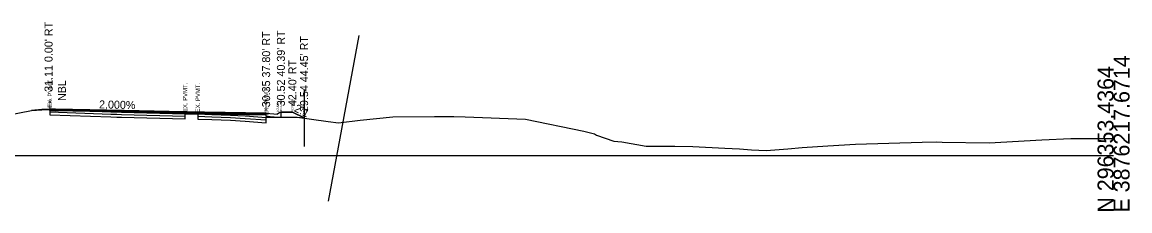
# Model space of a CAD drawing. Extents: x 14823 to 15251, y 114839 to 117377.
# Drawn here: x 15057.5 to 15251.2, y 114838.7 to 114871.6 of the extents above; entities that cross this region are included whole.
import ezdxf

# ---------------------------------------------------------------- set-up
doc = ezdxf.new("R2010")
doc.units = 0
for name, color, linetype in [('Default', 7, 'Continuous'), ('Level 1', 7, 'Continuous'), ('Level 10', 7, 'Continuous'), ('Level 11', 7, 'Continuous'), ('Level 2', 7, 'Continuous'), ('Level 25', 7, 'Continuous'), ('Level 3', 7, 'Continuous'), ('Level 4', 7, 'Continuous'), ('Level 42', 7, 'Continuous'), ('Level 49', 7, 'Continuous'), ('Level 50', 7, 'Continuous'), ('Level 52', 7, 'Continuous'), ('Level 53', 7, 'Continuous'), ('Level 56', 7, 'Continuous'), ('Level 59', 7, 'Continuous'), ('Level 63', 7, 'Continuous')]:
    doc.layers.add(name, color=color, linetype=linetype)

msp = doc.modelspace()

# ---------------------------------------------------------------- linework, layer by layer
at = {"layer": 'Default'}
msp.add_line((15116.36, 114869.31), (15111.04, 114840.38), dxfattribs=at)
at = {"layer": 'Level 1'}
for p, q in [((15055.25, 114855.46), (15059.13, 114856.19)), ((15059.13, 114856.19), (15060.97, 114856.3)), ((15060.97, 114856.3), (15062.37, 114856.39)), ((15062.37, 114856.39), (15073.01, 114856)), ((15073.01, 114856), (15074.04, 114855.95)), ((15074.04, 114855.95), (15074.87, 114855.93)), ((15074.87, 114855.93), (15086.01, 114855.65)), ((15086.01, 114855.65), (15087.32, 114855.63)), ((15087.32, 114855.63), (15088.22, 114855.61)), ((15088.22, 114855.61), (15090.68, 114855.53)), ((15090.68, 114855.53), (15093.96, 114855.41)), ((15093.96, 114855.41), (15096.52, 114855.25)), ((15096.52, 114855.25), (15100.16, 114854.99)), ((15100.16, 114854.99), (15103.18, 114855.05)), ((15103.18, 114855.05), (15105.58, 114855.07)), ((15105.58, 114855.07), (15111.03, 114854.31)), ((15111.03, 114854.31), (15112.81, 114854.04)), ((15112.81, 114854.04), (15116.6, 114854.53)), ((15116.6, 114854.53), (15122.34, 114855.13)), ((15122.34, 114855.13), (15129.6, 114855.16)), ((15129.6, 114855.16), (15133.02, 114855.14)), ((15133.02, 114855.14), (15134.95, 114855.09)), ((15134.95, 114855.09), (15145.51, 114854.67)), ((15145.51, 114854.67), (15155.71, 114852.62)), ((15155.71, 114852.62), (15157.59, 114852.13)), ((15157.59, 114852.13), (15157.94, 114851.9)), ((15157.94, 114851.9), (15160.99, 114850.86)), ((15160.99, 114850.86), (15162.4, 114850.72)), ((15162.4, 114850.72), (15166.62, 114849.98)), ((15203.24, 114850.32), (15214.91, 114850.66)), ((15214.91, 114850.66), (15217.39, 114850.71)), ((15217.39, 114850.71), (15218.37, 114850.7)), ((15218.37, 114850.7), (15226.61, 114850.54)), ((15226.61, 114850.54), (15235.79, 114851.06)), ((15235.79, 114851.06), (15240.88, 114851.3)), ((15240.88, 114851.3), (15248.36, 114851.31)), ((15166.62, 114849.98), (15171.65, 114849.95)), ((15171.65, 114849.95), (15174.8, 114849.92)), ((15174.8, 114849.92), (15180.38, 114849.61)), ((15180.38, 114849.61), (15182.97, 114849.49)), ((15182.97, 114849.49), (15185.07, 114849.36)), ((15185.07, 114849.36), (15187.62, 114849.19)), ((15187.62, 114849.19), (15191.41, 114849.52)), ((15191.41, 114849.52), (15193.91, 114849.77)), ((15193.91, 114849.77), (15198.4, 114850.01)), ((15198.4, 114850.01), (15203.24, 114850.32))]:
    msp.add_line(p, q, dxfattribs=at)
at = {"layer": 'Level 10'}
for p, q in [((15060.97, 114856.3), (15060.97, 114856.38)), ((15062.37, 114856.35), (15062.37, 114856.47)), ((15062.37, 114856.18), (15062.37, 114856.35)), ((15062.37, 114856.35), (15063.36, 114856.33)), ((15062.37, 114856.18), (15063.36, 114856.16)), ((15075.36, 114856.09), (15063.36, 114856.33)), ((15075.36, 114855.92), (15063.36, 114856.16)), ((15085.86, 114855.88), (15075.36, 114856.09)), ((15085.86, 114855.71), (15075.36, 114855.92)), ((15085.86, 114855.88), (15100.17, 114855.59)), ((15085.86, 114855.71), (15100.17, 114855.43)), ((15100.17, 114855.59), (15100.17, 114855.72)), ((15100.17, 114855.43), (15100.17, 114855.59))]:
    msp.add_line(p, q, dxfattribs=at)
at = {"layer": 'Level 11'}
for p, q in [((15062.37, 114856.47), (15062.37, 114856.18)), ((15100.17, 114855.14), (15100.17, 114855.72)), ((15102.17, 114854.97), (15100.17, 114855.14)), ((15102.76, 114854.97), (15102.17, 114854.97)), ((15102.76, 114855.89), (15102.76, 114854.97))]:
    msp.add_line(p, q, dxfattribs=at)
at = {"layer": 'Level 2'}
for p, q in [((15060.97, 114856.38), (15062.37, 114856.47)), ((15062.37, 114856.47), (15063.36, 114856.45)), ((15063.36, 114856.45), (15075.36, 114856.21)), ((15075.36, 114856.21), (15085.86, 114856)), ((15085.86, 114856), (15100.17, 114855.72))]:
    msp.add_line(p, q, dxfattribs=at)
at = {"layer": 'Level 25'}
msp.add_line((15106.81, 114859.9), (15106.81, 114849.9), dxfattribs=at)
at = {"layer": 'Level 3'}
for p, q in [((15060.97, 114856.38), (15059.13, 114856.19)), ((15100.17, 114855.72), (15102.17, 114855.55)), ((15102.17, 114855.64), (15102.59, 114855.89)), ((15102.17, 114855.55), (15102.17, 114855.64)), ((15102.59, 114855.89), (15102.76, 114855.89))]:
    msp.add_line(p, q, dxfattribs=at)
at = {"layer": 'Level 4'}
for p, q in [((15102.76, 114855.89), (15104.76, 114855.93)), ((15104.76, 114855.93), (15106.81, 114854.9))]:
    msp.add_line(p, q, dxfattribs=at)
at = {"layer": 'Level 50'}
for points in [[(15101.58, 114855.02), (15100.17, 114855.14), (15100.17, 114855.72), (15085.86, 114856), (15075.36, 114856.21), (15063.36, 114856.45), (15062.37, 114856.47), (15060.97, 114856.38), (15059.13, 114856.19), (15060.97, 114856.3), (15062.37, 114856.39), (15073.01, 114856), (15074.04, 114855.95), (15074.87, 114855.93), (15086.01, 114855.65), (15087.32, 114855.63), (15088.22, 114855.61), (15090.68, 114855.53), (15093.96, 114855.41), (15096.52, 114855.25), (15100.16, 114854.99)], [(15101.58, 114855.02), (15100.17, 114855.14), (15100.17, 114855.72), (15085.86, 114856), (15075.36, 114856.21), (15063.36, 114856.45), (15062.37, 114856.47), (15060.97, 114856.38), (15059.13, 114856.19), (15060.97, 114856.3), (15062.37, 114856.39), (15073.01, 114856), (15074.04, 114855.95), (15074.87, 114855.93), (15086.01, 114855.65), (15087.32, 114855.63), (15088.22, 114855.61), (15090.68, 114855.53), (15093.96, 114855.41), (15096.52, 114855.25), (15100.16, 114854.99)], [(15101.58, 114855.02), (15102.76, 114855.04), (15102.76, 114854.97), (15102.17, 114854.97)], [(15101.58, 114855.02), (15102.76, 114855.04), (15102.76, 114854.97), (15102.17, 114854.97)], [(15102.76, 114855.04), (15103.18, 114855.05), (15105.58, 114855.07), (15106.81, 114854.9), (15104.76, 114855.93), (15102.76, 114855.89)], [(15102.76, 114855.04), (15103.18, 114855.05), (15105.58, 114855.07), (15106.81, 114854.9), (15104.76, 114855.93), (15102.76, 114855.89)]]:
    msp.add_lwpolyline(points, close=True, dxfattribs=at)
at = {"layer": 'Level 59'}
for p, q in [((15062.37, 114856.39), (15062.37, 114855.97)), ((15062.37, 114855.97), (15073.01, 114855.58)), ((15062.37, 114855.97), (15062.37, 114855.47)), ((15062.37, 114855.47), (15073.01, 114855.08)), ((15073.01, 114855.58), (15074.04, 114855.54)), ((15073.01, 114855.08), (15074.04, 114855.04)), ((15074.04, 114855.54), (15074.87, 114855.52)), ((15074.04, 114855.04), (15074.87, 114855.02)), ((15074.87, 114855.52), (15086.01, 114855.23)), ((15074.87, 114855.02), (15086.01, 114854.73)), ((15086.01, 114855.23), (15086.01, 114855.65)), ((15086.01, 114854.73), (15086.01, 114855.23)), ((15088.22, 114855.61), (15088.22, 114855.2)), ((15088.22, 114855.2), (15090.68, 114855.11)), ((15088.22, 114855.2), (15088.22, 114854.7)), ((15088.22, 114854.7), (15090.68, 114854.61)), ((15090.68, 114855.11), (15093.96, 114854.99)), ((15090.68, 114854.61), (15093.96, 114854.49)), ((15093.96, 114854.99), (15096.52, 114854.83)), ((15093.96, 114854.49), (15096.52, 114854.33)), ((15096.52, 114854.83), (15100.16, 114854.58)), ((15096.52, 114854.33), (15100.16, 114854.08)), ((15100.16, 114854.58), (15100.16, 114854.99)), ((15100.16, 114854.58), (15100.16, 114854.58)), ((15100.16, 114854.08), (15100.16, 114854.58)), ((15100.16, 114854.08), (15100.16, 114854.08))]:
    msp.add_line(p, q, dxfattribs=at)
at = {"layer": 'Level 63'}
msp.add_line((15048.36, 114848.36), (15248.36, 114848.36), dxfattribs=at)

# ---------------------------------------------------------------- texts
at = {"layer": 'Level 42'}
msp.add_text('NBL', height=1.4, rotation=90, dxfattribs=at).set_placement((15065.16, 114857.87))
at = {"layer": 'Level 49'}
msp.add_text('2.000%', height=1.4, rotation=358.8542, dxfattribs=at).set_placement((15070.95, 114856.58))
at = {"layer": 'Level 50'}
msp.add_text('2:1', height=1.4, rotation=333.4878, dxfattribs=at).set_placement((15104.97, 114856.14))
at = {"layer": 'Level 52'}
for s, p in [("31.11 0.00' RT", (15062.83, 114859.47)), ("30.35 37.80' RT", (15100.87, 114856.77)), ("30.52 40.39' RT", (15103.46, 114856.94)), ("29.54 44.45' RT", (15107.51, 114855.95)), ("42.40' RT", (15105.46, 114856.98))]:
    msp.add_text(s, height=1.4, rotation=90, dxfattribs=at).set_placement(p)
at = {"layer": 'Level 53'}
for p in [(15062.75, 114856.39), (15086.38, 114855.65), (15088.6, 114855.61), (15100.54, 114854.99)]:
    msp.add_text(' EX. PVMT.', height=0.75, rotation=90, dxfattribs=at).set_placement(p)
at = {"layer": 'Level 56'}
for s, p in [('EOPLIN', (15062.55, 114856.47)), ('BKCURBR', (15102.93, 114855.89)), ('RCVRBLR', (15104.94, 114855.93)), ('EOPROUT', (15100.34, 114855.72)), ('FLCURBR', (15102.35, 114855.64)), ('FRDTCHR', (15106.99, 114854.9))]:
    msp.add_text(s, height=0.35, rotation=90, dxfattribs=at).set_placement(p)
at = {"layer": 'Level 63'}
for s, p in [('E 3876217.6714', (15251.16, 114838.37)), ('N 296353.4364', (15248.36, 114838.36))]:
    msp.add_text(s, height=2.8, rotation=90, dxfattribs=at).set_placement(p)

doc.saveas('drawing.dxf')
